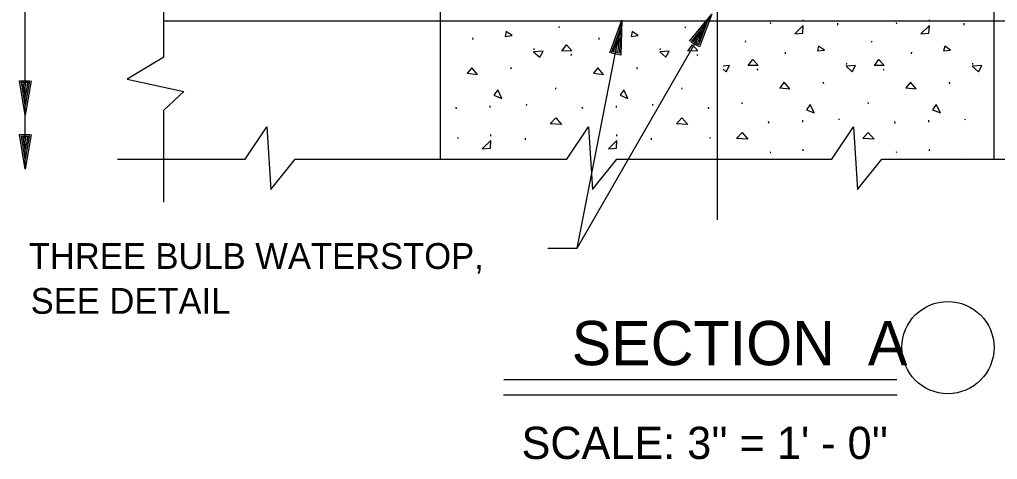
# Model space of a CAD drawing. Extents: x 44743.44 to 44747.1, y 44738.46 to 44741.29.
# Drawn here: x 44744.0402 to 44744.4817, y 44739.3735 to 44739.5722 of the extents above; entities that cross this region are included whole.
import ezdxf

# ---------------------------------------------------------------- set-up
doc = ezdxf.new("R2010")
doc.units = 0
for name, color, linetype in [('Level 1', 7, 'Continuous'), ('Level 10', 7, 'Continuous'), ('Level 2', 7, 'Continuous'), ('Level 3', 7, 'Continuous'), ('Level 8', 7, 'Continuous'), ('S-ANNO-TEXT', 7, 'Continuous')]:
    doc.layers.add(name, color=color, linetype=linetype)

msp = doc.modelspace()

# ---------------------------------------------------------------- linework, layer by layer
at = {"layer": 'Level 1'}
for p, q in [((44744.35524, 44739.48171), (44744.35524, 44739.90439)), ((44744.10524, 44739.55528), (44744.10524, 44739.72682)), ((44744.04274, 44739.50466), (44744.04274, 44739.66744)), ((44744.35051, 44739.57089), (44744.35051, 44739.57089)), ((44744.04016, 44739.54458), (44744.04016, 44739.54458)), ((44744.04099, 44739.54391), (44744.04099, 44739.54391)), ((44744.04183, 44739.54325), (44744.04183, 44739.54325)), ((44744.04274, 44739.54183), (44744.04274, 44739.54183)), ((44744.04299, 44739.54325), (44744.04299, 44739.54325)), ((44744.04383, 44739.54391), (44744.04383, 44739.54391)), ((44744.04458, 44739.54458), (44744.04458, 44739.54458)), ((44744.04533, 44739.54458), (44744.04533, 44739.54458)), ((44744.10524, 44739.48978), (44744.10524, 44739.53132)), ((44744.04274, 44739.509), (44744.04274, 44739.509)), ((44744.08436, 44739.50911), (44744.14202, 44739.50911)), ((44744.16457, 44739.50911), (44744.28729, 44739.50911)), ((44744.30982, 44739.50911), (44744.40696, 44739.50911)), ((44744.42949, 44739.50911), (44744.53486, 44739.50911)), ((44744.04274, 44739.50466), (44744.04274, 44739.50466))]:
    msp.add_line(p, q, dxfattribs=at)
for points in [[(44744.10524, 44739.55528), (44744.0888, 44739.54523), (44744.11438, 44739.53975), (44744.10524, 44739.53132)], [(44744.04533, 44739.54458), (44744.04274, 44739.529), (44744.04016, 44739.54458), (44744.04458, 44739.54458), (44744.04274, 44739.53333), (44744.04099, 44739.54391), (44744.04383, 44739.54391), (44744.04274, 44739.5375), (44744.04183, 44739.54325), (44744.04299, 44739.54325), (44744.04274, 44739.54183)], [(44744.14202, 44739.50911), (44744.15177, 44739.52372), (44744.1536, 44739.49541), (44744.16457, 44739.50911)], [(44744.28729, 44739.50911), (44744.29704, 44739.52372), (44744.29886, 44739.49541), (44744.30982, 44739.50911)], [(44744.40696, 44739.50911), (44744.41671, 44739.52372), (44744.41854, 44739.49541), (44744.42949, 44739.50911)], [(44744.04533, 44739.52025), (44744.04274, 44739.50466), (44744.04016, 44739.52025), (44744.04458, 44739.52025), (44744.04274, 44739.509), (44744.04099, 44739.51958), (44744.04383, 44739.51958), (44744.04274, 44739.51316), (44744.04183, 44739.51891), (44744.04299, 44739.51891), (44744.04274, 44739.5175)]]:
    msp.add_lwpolyline(points, dxfattribs=at)
at = {"layer": 'Level 10'}
for p, q in [((44744.23024, 44739.50911), (44744.23024, 44739.64661)), ((44744.48024, 44739.50911), (44744.48024, 44739.64661)), ((44744.25886, 44739.40965), (44744.43618, 44739.40965)), ((44744.25863, 44739.40272), (44744.43645, 44739.40272))]:
    msp.add_line(p, q, dxfattribs=at)
at = {"layer": 'Level 2'}
for p, q in [((44744.29191, 44739.46892), (44744.35267, 44739.57465)), ((44744.10524, 44739.57161), (44744.60524, 44739.57161)), ((44744.29191, 44739.46892), (44744.31214, 44739.57201)), ((44744.27866, 44739.46892), (44744.29191, 44739.46892))]:
    msp.add_line(p, q, dxfattribs=at)
for points in [[(44744.34267, 44739.56242), (44744.35267, 44739.57465), (44744.34715, 44739.55985), (44744.34332, 44739.56206), (44744.35051, 44739.57089), (44744.34675, 44739.56085), (44744.3443, 44739.56226), (44744.34843, 44739.56729), (44744.34637, 44739.56184), (44744.34536, 44739.56242), (44744.34627, 44739.56353)], [(44744.30661, 44739.55721), (44744.31214, 44739.57201), (44744.31167, 44739.55621), (44744.30734, 44739.55707), (44744.31131, 44739.56776), (44744.31098, 44739.55703), (44744.3082, 44739.55758), (44744.3105, 44739.56366), (44744.3103, 44739.55785), (44744.30915, 44739.55807), (44744.30967, 44739.55941)]]:
    msp.add_lwpolyline(points, dxfattribs=at)
at = {"layer": 'Level 3'}
msp.add_circle((44744.4593, 44739.42403), 0.02083, dxfattribs=at)
at = {"layer": 'Level 8'}
for p, q in [((44744.28371, 44739.56853), (44744.284, 44739.56914)), ((44744.31214, 44739.57201), (44744.31214, 44739.57201)), ((44744.34066, 44739.56853), (44744.34094, 44739.56914)), ((44744.37936, 44739.57029), (44744.37913, 44739.57085)), ((44744.394, 44739.57143), (44744.394, 44739.57216)), ((44744.40967, 44739.56976), (44744.40967, 44739.57054)), ((44744.4363, 44739.57029), (44744.43608, 44739.57085)), ((44744.45094, 44739.57143), (44744.45094, 44739.57216)), ((44744.46661, 44739.56976), (44744.46661, 44739.57054)), ((44744.24485, 44739.56328), (44744.24496, 44739.56404)), ((44744.30179, 44739.56328), (44744.30191, 44739.56404)), ((44744.31131, 44739.56776), (44744.31131, 44739.56776)), ((44744.27246, 44739.55853), (44744.27251, 44739.5591)), ((44744.32941, 44739.55853), (44744.32946, 44739.5591)), ((44744.36785, 44739.56194), (44744.36813, 44739.56256)), ((44744.42479, 44739.56194), (44744.42507, 44739.56256)), ((44744.2891, 44739.55592), (44744.28948, 44739.55658)), ((44744.34604, 44739.55592), (44744.34642, 44739.55658)), ((44744.38592, 44739.55669), (44744.38604, 44739.55745)), ((44744.44286, 44739.55669), (44744.44297, 44739.55745)), ((44744.26227, 44739.54983), (44744.26192, 44739.55052)), ((44744.31921, 44739.54983), (44744.31886, 44739.55052)), ((44744.41354, 44739.55194), (44744.41359, 44739.55252)), ((44744.47047, 44739.55194), (44744.47052, 44739.55252)), ((44744.37322, 44739.54934), (44744.37361, 44739.55)), ((44744.43016, 44739.54934), (44744.43056, 44739.55)), ((44744.28233, 44739.54076), (44744.28227, 44739.54139)), ((44744.33926, 44739.54076), (44744.33921, 44739.54139)), ((44744.40334, 44739.54325), (44744.40298, 44739.54393)), ((44744.46027, 44739.54325), (44744.45993, 44739.54393)), ((44744.2375, 44739.5319), (44744.23729, 44739.53268)), ((44744.25266, 44739.53253), (44744.25266, 44739.53331)), ((44744.26908, 44739.53345), (44744.26918, 44739.53404)), ((44744.29444, 44739.5319), (44744.29422, 44739.53268)), ((44744.3096, 44739.53253), (44744.3096, 44739.53331)), ((44744.32602, 44739.53345), (44744.32613, 44739.53404)), ((44744.35139, 44739.5319), (44744.35116, 44739.53268)), ((44744.36645, 44739.53417), (44744.3664, 44739.53481)), ((44744.42339, 44739.53417), (44744.42334, 44739.53481)), ((44744.37858, 44739.52532), (44744.37835, 44739.5261)), ((44744.39373, 44739.52594), (44744.39373, 44739.52672)), ((44744.41015, 44739.52687), (44744.41025, 44739.52745)), ((44744.43551, 44739.52532), (44744.4353, 44739.5261)), ((44744.45067, 44739.52594), (44744.45067, 44739.52672)), ((44744.46709, 44739.52687), (44744.46719, 44739.52745)), ((44744.25293, 44739.51957), (44744.25293, 44739.5203)), ((44744.30988, 44739.51957), (44744.30988, 44739.5203)), ((44744.23829, 44739.51842), (44744.23807, 44739.51898)), ((44744.2686, 44739.51789), (44744.2686, 44739.51867)), ((44744.32554, 44739.51789), (44744.32554, 44739.51867)), ((44744.35217, 44739.51842), (44744.35195, 44739.51898)), ((44744.37936, 44739.51184), (44744.37913, 44739.5124)), ((44744.394, 44739.51298), (44744.394, 44739.51371)), ((44744.45094, 44739.51298), (44744.45094, 44739.51371))]:
    msp.add_line(p, q, dxfattribs=at)
for points in [[(44744.39381, 44739.56601), (44744.394, 44739.56948), (44744.39015, 44739.56572)], [(44744.45074, 44739.56601), (44744.45094, 44739.56948), (44744.44709, 44739.56572)], [(44744.25934, 44739.56465), (44744.2625, 44739.56505), (44744.25985, 44739.56684)], [(44744.31629, 44739.56465), (44744.31944, 44739.56505), (44744.31679, 44739.56684)], [(44744.285, 44739.55798), (44744.2871, 44739.56076), (44744.28946, 44739.55809)], [(44744.34194, 44739.55798), (44744.34405, 44739.56076), (44744.3464, 44739.55809)], [(44744.40041, 44739.55807), (44744.40358, 44739.55846), (44744.40092, 44739.56026)], [(44744.45735, 44739.55807), (44744.46051, 44739.55846), (44744.45786, 44739.56026)], [(44744.27227, 44739.55768), (44744.27505, 44739.5552), (44744.27652, 44739.55798)], [(44744.32921, 44739.55768), (44744.33198, 44739.5552), (44744.33347, 44739.55798)], [(44744.24692, 44739.54748), (44744.24434, 44739.55045), (44744.24227, 44739.548)], [(44744.30386, 44739.54748), (44744.30129, 44739.55045), (44744.29921, 44739.548)], [(44744.36913, 44739.5514), (44744.37123, 44739.55417), (44744.37359, 44739.55151)], [(44744.41334, 44739.5511), (44744.41611, 44739.54862), (44744.4176, 44739.5514)], [(44744.42608, 44739.5514), (44744.42817, 44739.55417), (44744.43052, 44739.55151)], [(44744.47027, 44739.5511), (44744.47306, 44739.54862), (44744.47454, 44739.5514)], [(44744.38798, 44739.5409), (44744.38541, 44739.54387), (44744.38334, 44739.54141)], [(44744.44493, 44739.5409), (44744.44235, 44739.54387), (44744.44027, 44739.54141)], [(44744.25436, 44739.538), (44744.25791, 44739.53661), (44744.25604, 44739.54045)], [(44744.3113, 44739.538), (44744.31485, 44739.53661), (44744.31297, 44739.54045)], [(44744.39542, 44739.53141), (44744.39897, 44739.53003), (44744.3971, 44739.53387)], [(44744.45236, 44739.53141), (44744.45592, 44739.53003), (44744.45405, 44739.53387)], [(44744.27977, 44739.52512), (44744.28224, 44739.5278), (44744.2849, 44739.52483)], [(44744.33671, 44739.52512), (44744.33918, 44739.5278), (44744.34184, 44739.52483)], [(44744.3639, 44739.51854), (44744.36637, 44739.52121), (44744.36902, 44739.51825)], [(44744.42084, 44739.51854), (44744.42332, 44739.52121), (44744.42597, 44739.51825)], [(44744.25274, 44739.51414), (44744.25293, 44739.51762), (44744.24908, 44739.51385)], [(44744.30968, 44739.51414), (44744.30988, 44739.51762), (44744.30602, 44739.51385)]]:
    msp.add_lwpolyline(points, close=True, dxfattribs=at)
for points in [[(44744.36066, 44739.5514), (44744.35784, 44739.5512)], [(44744.35917, 44739.54862), (44744.36066, 44739.5514)], [(44744.35784, 44739.54981), (44744.35917, 44739.54862)], [(44744.43623, 44739.51201), (44744.43608, 44739.5124)], [(44744.46661, 44739.51201), (44744.46661, 44739.51209)]]:
    msp.add_lwpolyline(points, dxfattribs=at)

# ---------------------------------------------------------------- texts
at = {"layer": 'Level 3'}
msp.add_text('SECTION  A', height=0.02, dxfattribs=at).set_placement((44744.28942, 44739.41606))
at = {"layer": 'S-ANNO-TEXT'}
for s, height, p in [('THREE BULB WATERSTOP,', 0.0116667, (44744.0443, 44739.45957)), ('SEE DETAIL', 0.011667, (44744.04518, 44739.4393)), ("SCALE: 3'' = 1' - 0''", 0.0145833, (44744.2668, 44739.3737))]:
    msp.add_text(s, height=height, dxfattribs=at).set_placement(p)

doc.saveas('drawing.dxf')
